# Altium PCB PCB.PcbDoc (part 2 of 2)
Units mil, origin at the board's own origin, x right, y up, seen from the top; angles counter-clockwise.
Board outline 5216.54 x 1820.87 mil, 2 copper layers (Top Layer, Bottom Layer), stack 62 mil thick; 55 components, 32 nets, 136 pads, 25 vias.
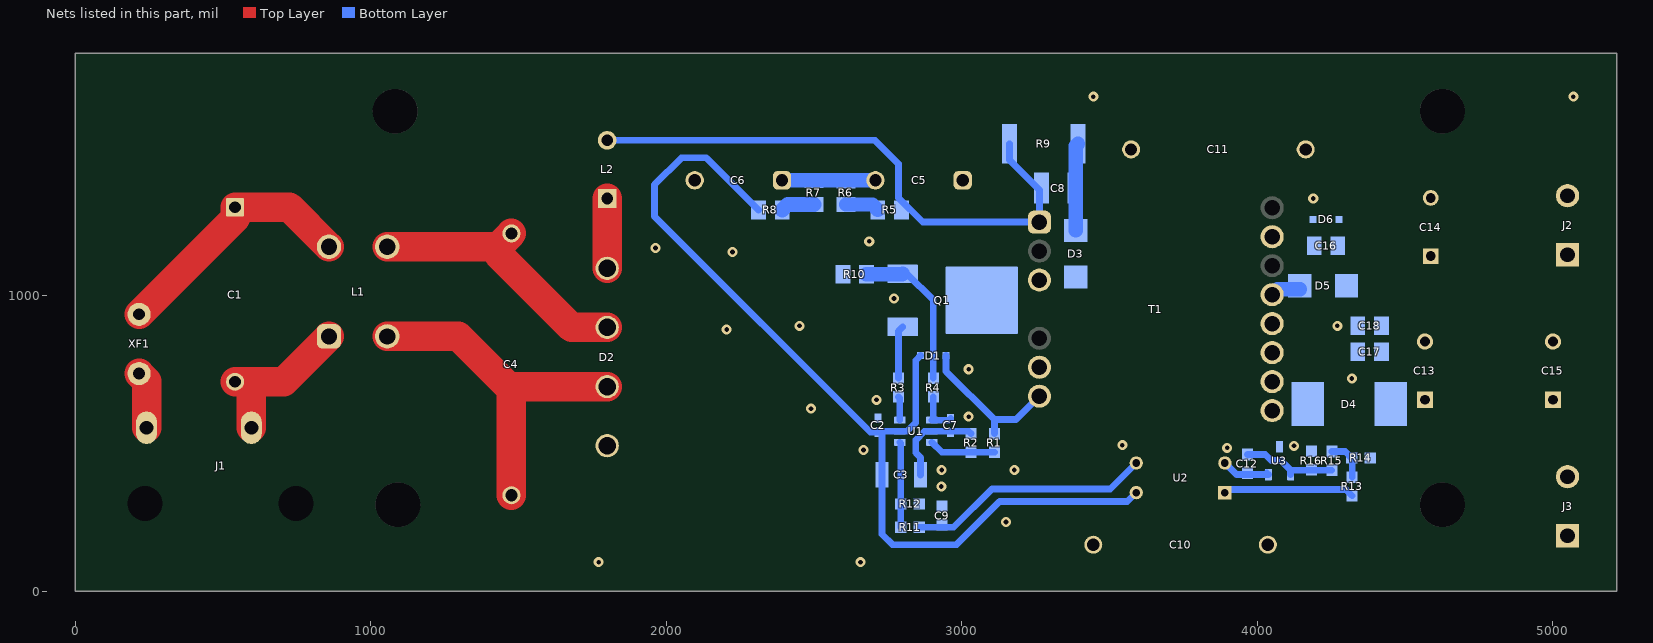
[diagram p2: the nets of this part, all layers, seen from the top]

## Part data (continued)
R13: library part CMP-0022588-5, "RES, 750, 1%, 0.1 W, AEC-Q200 Grade 0, 0603", Manufacturer=Vishay-Dale, Power_W=100mW, Supplier Part Number 1=541-750HCT-ND, TempCo="100 ppm/C", Tolerance_%=1%, Value2=0.1W, Value_Code=750R, ValueDisplayed=750
R14: library part CMP-0025697-4, "RES, 0, 5%, 0.1 W, AEC-Q200 Grade 0, 0603", Manufacturer=Vishay-Dale, Power_W=100mW, Supplier Part Number 1=541-0.0GCT-ND, TempCo="200 ppm/C", Tolerance_%=5%, Value2=0.1W, Value_Code=0000, ValueDisplayed=0
R15: library part CMP-0022651-4, "RES, 90.9 k, 1%, 0.1 W, AEC-Q200 Grade 0, 0603", Manufacturer=Vishay-Dale, Power_W=100mW, Supplier Part Number 1=541-90.9KHCT-ND, TempCo="100 ppm/C", Tolerance_%=1%, Value2=0.1W, Value_Code=90k9, ValueDisplayed=90.9k
R16: library part CMP-0022410-4, "RES, 40.2 k, 1%, 0.1 W, AEC-Q200 Grade 0, 0603", Manufacturer=Vishay-Dale, Power_W=100mW, Supplier Part Number 1=541-40.2KHCT-ND, TempCo="100 ppm/C", Tolerance_%=1%, Value2=0.1W, Value_Code=40k2, ValueDisplayed=40.2k
T1: library part CMP-0081896-1, "Transformer, 2900 uH, TH", Manufacturer="Wurth Elektronik"
U1: library part CMP-0078369-1, "High-Efficiency Low-Cost Flyback Controller with Secondary-Side Regulation, DBV0006A (SOT-23-6)", Alternate Manufacturer="Texas Instruments"
U2: library part CMP-0006173-1, "Optocoupler, 5 kV, 80-160% CTR, TH", Manufacturer="Fairchild Semiconductor", Supplier Part Number 1=FOD817A-ND, Voltage_Isolation_Vrms=5kV
U3: library part CMP-0033048-1, "Low Voltage Adjustable Precision Shunt Regulator, 39 ppm / degC, 15 mA, 0 to 70 degC, 3-pin SOT-23 (DBZ), Green (RoHS & no Sb/Br)", Manufacturer="Texas Instruments", Rating=Catalog, Temp Coeff(Max)(ppm/ degree C)=129, Temp Coeff(Typ)(ppm/ degree C)=39
XF1: library part CMP-0003627-1, "Fuse Holder, TR5, TH", Manufacturer=Littelfuse, Supplier Part Number 1=WK6235-ND

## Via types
v1: diameter 34, hole 16, Top Layer to Bottom Layer, 24 vias
v2: diameter 34, hole 16, Top Layer to Bottom Layer, tented both sides, 1 vias

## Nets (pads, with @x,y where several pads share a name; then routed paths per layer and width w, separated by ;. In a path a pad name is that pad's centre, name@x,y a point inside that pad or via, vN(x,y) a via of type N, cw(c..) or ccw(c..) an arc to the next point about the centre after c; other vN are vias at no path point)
AGND: C11.1 C14.2 C16.2 D6.2 J2.2 T1.13
  other v1: 4188.97,1328.74 5068.9,1673.23
Bias: D1.2 R1.2 T1.6 | length 516.8
  Bottom Layer w23: D1.2@2946.85,797.24 2946.85,744.09 3110.24,580.71 ; R1.2@3110.24,533.25 3110.24,580.71 ; T1.6@3262.62,659.82 3183.51,580.71 3110.24,580.71
FB: R11.1 R12.2 U1.1 | length 288.6
  Bottom Layer w23: U1.1@2790.35,503.94 2793.31,500.98 R11.1@2793.31,216.54
NetC1_1: C1.1 L1.4 XF1.1 | length 870.3
  Top Layer w100: XF1.1@216.54,936.61 541.34,1261.42 C1.1@541.34,1299.21 725.24,1299.21 L1.4@859.09,1165.35
NetC1_2: C1.2 J1.2 L1.1 | length 538.5
  Top Layer w100: C1.2@541.34,708.66 600.39,708.66 ; J1.2@596.46,553.15 596.46,704.72 600.39,708.66 ; L1.1@859.09,862.2 705.55,708.66 600.39,708.66
NetC4_1: C4.1 D2.3 L1.2 | length 1172.4
  Top Layer w100: L1.2@1055.94,862.2 1296.85,862.2 1466.54,692.52 ; C4.1@1476.38,324.8 1476.38,692.52 D2.3@1800.17,692.52
NetC4_2: C4.2 D2.2 L1.3 | length 935.1
  Top Layer w100: L1.3@1055.94,1165.35 1431.1,1165.35 ; C4.2@1476.38,1210.63 1431.1,1165.35 ; D2.2@1800.17,892.52 1680.31,892.52 1431.1,1141.72 1431.1,1165.35
NetC5_2: C5.2 C6.1 R6.1 R7.2 | length 315.9
  Bottom Layer w50: C6.1@2391.73,1390.38 C5.2@2707.68,1390.38
NetC7_1: C7.1 R4.1 U1.4 | length 147.2
  Bottom Layer w23: R4.1@2903.54,657.46 2903.54,583.66 U1.4@2898.62,578.74 2956.69,578.74 C7.1@2962.6,584.65
NetC8_2: C8.2 D3.1 R9.1 | length 296.6
  Bottom Layer w48: D3.1@3385.83,1220.47 3385.83,1506.44 R9.1@3393.33,1513.95
NetC9_1: C9.1 R11.2 U2.3 | length 823.9
  Bottom Layer w23: R11.2@2856.3,216.54 2972.44,216.54 3101.92,346.01 3502.31,346.01 U2.3@3590.16,433.86
NetC12_1: C12.1 R15.1 R16.2 U3.1 | length 322.3
  Bottom Layer w23: C12.1@3966.53,462.77 4026.65,462.77 4047.45,441.97 4079.85,441.97 U3.1@4112.2,409.62 ; U3.1@4112.2,394.72 U3.1@4112.2,409.62 ; R15.1@4251.96,409.62 U3.1@4112.2,409.62
NetC12_2: C12.2 U2.2 U3.2 | length 171.7
  Bottom Layer w23: U2.2@3890.16,433.86 3929.29,394.72 U3.2@4037.4,394.72 U3.2@4031.56,400.56
NetD2_1: D2.1 L2.1 | length 236.2
  Top Layer w100: D2.1@1800.17,1092.52 L2.1@1800.17,1328.74
NetD3_2: D3.2 Q1.4 T1.3
NetD4_2: D4.2 T1.7 T1.8
NetD5_2: D5.2 T1.11 | length 101.3
  Bottom Layer w48: T1.11@4050.02,1003.33 4068.46,1021.76 D5.2@4143.7,1021.76
NetJ1_1: J1.1 XF1.2 | length 194.1
  Top Layer w100: XF1.2@216.54,736.61 242.13,711.02 J1.1@242.13,553.15
NetQ1_1: Q1.1 R3.2 | length 180.1
  Bottom Layer w23: R3.2@2785.43,720.45 2785.43,879.9 Q1.1@2800.02,894.49
NetQ1_3: Q1.3 R4.2 R10.2 | length 527.7
  Bottom Layer w23: Q1.3@2800.02,1074.02 2814.59,1074.02 2903.54,985.06 R4.2@2903.54,720.45
  Bottom Layer w50: R10.2@2677.8,1072.83 2798.84,1072.83 Q1.3@2800.02,1074.02
NetR1_1: R1.1 R2.2 U1.6 | length 225.6
  Bottom Layer w23: U1.6@2898.62,503.94 2932.3,470.26 R1.1@3110.24,470.26
NetR3_1: R3.1 U1.3 | length 80.8
  Bottom Layer w23: R3.1@2785.43,657.46 2790.35,652.54 U1.3@2790.35,578.74
NetR5_1: R5.1 R6.2 | length 115.3
  Bottom Layer w48: R6.2@2608.27,1308.43 2697.47,1308.43 R5.1@2715.91,1289.98
NetR7_1: R7.1 R8.2 | length 115.4
  Bottom Layer w50: R8.2@2392.36,1289.98 2411.12,1308.74 R7.1@2500,1308.74
NetR13_1: R13.1 U2.1 | length 444
  Bottom Layer w23: U2.1@3890.16,333.86 3900.79,344.49 4299.51,344.49 R13.1@4320.86,323.14
NetR13_2: R13.2 R14.1 R15.2 | length 141.5
  Bottom Layer w23: R15.2@4251.96,472.61 4297.24,472.61 R14.1@4318.89,450.95 4320.86,448.99 R13.2@4320.86,386.13
PGND: C2.2 C3.2 C6.2 C7.2 C9.2 C10.2 C11.2 D2.4 R2.1 R10.1 R12.1 T1.5 U1.5 | length 327.2
  Bottom Layer w23: C3.2@2860.24,393.7 2860.24,452.76 2844.49,468.5 2844.49,511.81 2874.02,541.34 U1.5@2898.62,541.34 3023.41,541.34 R2.1@3031.5,533.25
  other v1: 1771.65,98.43 2657.48,98.43 3149.61,234.62 2930.81,354.33 2932.09,410.47 3177.59,410.47 2667.77,478.27 3543.31,494.13 3023.41,590.55 2490.16,617.78 2711.8,647.8 3023.41,751.14 2204.72,885.83 2450.79,898.17 2770.44,990.16 2224.41,1147.83 1963.56,1161.42 2687.01,1183.69 3445.2,1673.23
SGND: C10.1 C13.2 C15.2 C17.2 C18.2 J3.1 R16.1 T1.9 T1.10 U3.3
  other v1: 3897.64,485.23 4319.71,720.06 4270.67,898.17
  other v2: 4124.02,492.13
Vaux: C14.1 C16.1 D5.1 D6.1 J2.1
VBulk: C5.1 C8.1 L2.2 R5.2 R9.2 T1.1 | length 1952
  Bottom Layer w23: L2.2@1800.17,1525.59 2706.69,1525.59 2786.06,1446.22 2786.06,1330.69 2867.96,1248.8 T1.1@3262.62,1248.8 3262.62,1357.1 3161.05,1458.67 R9.2@3161.05,1513.95
VDD: C2.1 C3.1 D1.1 R8.1 U1.2 U2.4 | length 3309.4
  Bottom Layer w23: R8.1@2312.36,1289.98 2135.81,1466.54 2051.67,1466.54 1960.67,1375.54 1960.67,1267.67 2690.23,538.11 C2.1@2716.54,538.11 ; D1.1@2860.24,797.24 2844.49,781.5 2844.49,570.87 2814.96,541.34 U1.2@2790.35,541.34 2719.76,541.34 C2.1@2716.54,538.11 ; U2.4@3590.16,333.86 3559.75,303.45 3128.25,303.45 2982.28,157.48 2765.75,157.48 2730.32,192.91 C3.1@2730.32,393.7 2730.32,538.11 C2.1@2716.54,538.11
Vout: C13.1 C15.1 C17.1 C18.1 D4.1 J3.2 R14.2
pads on no net: H1.0 H1.MH H2.0 H2.MH H3.0 H3.MH H4.0 H4.MH J1.MH1 J1.MH2 T1.2 T1.4 T1.12 T1.14

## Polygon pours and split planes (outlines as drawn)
PGND on Bottom Layer "BOTTOM_LAYER_PGND_P016" (solid, remove dead copper, pour order 16): 3612.2,49.21 3612.2,1771.65 1919.29,1771.65 1919.29,639.76 1870.08,590.55 1712.6,590.55 1712.6,49.21
VBulk on Bottom Layer "BOTTOM_LAYER_VBULK_P014" (solid, remove dead copper, pour order 14): 3326.77,1771.65
VBulk on Bottom Layer "BOTTOM_LAYER_VBULK_P000" (solid, remove dead copper, pour order 0): 1722.44,1771.65 1722.44,1476.38 1801.18,1397.64 2717.5,1397.64 2755.91,1359.24 2755.91,1141.73 3326.77,1141.73 3326.77,1771.65
SGND on Bottom Layer "BOTTOM_LAYER_SGND_P012" (solid, remove dead copper, pour order 12): 5167.32,944.88 3868.11,944.88 3868.11,49.21 5167.32,49.21
NetD4_2 on Bottom Layer "BOTTOM_LAYER_NETD4_2_P010" (solid, remove dead copper, pour order 10): 4005.91,748.03 4192.91,748.03 4232.28,708.66 4232.28,551.18 4045.28,551.18 4005.91,590.55
Vout on Bottom Layer "BOTTOM_LAYER_VOUT_P008" (solid, remove dead copper, pour order 8): 5167.32,944.88 4379.92,944.88 4379.92,295.28 5167.32,295.28
AGND on Bottom Layer "BOTTOM_LAYER_AGND_P006" (solid, remove dead copper, pour order 6): 3937.01,1122.05 3937.01,1771.65 5167.32,1771.65 5167.32,1122.05
Vaux on Bottom Layer "BOTTOM_LAYER_VAUX_P004" (solid, remove dead copper, pour order 4): 4232.28,1279.53 5167.32,1279.53 5167.32,984.25 4232.28,984.25
NetD3_2 on Bottom Layer "BOTTOM_LAYER_NETD3_2_P002" (solid, remove dead copper, pour order 2): 2933.07,1112.2 3444.88,1112.2 3444.88,1033.46 3277.56,866.14 2933.07,866.14
SGND on Top Layer "TOP_LAYER_SGND_P022" (solid, remove dead copper, pour order 22): 5167.32,944.88 3868.11,944.88 3868.11,49.21 5167.32,49.21
AGND on Top Layer "TOP_LAYER_AGND_P020" (solid, remove dead copper, pour order 20): 5167.32,1771.65 3937.01,1771.65 3937.01,984.25 5167.32,984.25
PGND on Top Layer "TOP_LAYER_PGND_P018" (solid, remove dead copper, pour order 18): 3612.2,1771.65 1919.29,1771.65 1919.29,639.76 1870.08,590.55 1712.6,590.55 1712.6,49.21 3612.2,49.21

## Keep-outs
Keep-Out Layer:
  text ".Layer_Name" at 577,-858.49 h60

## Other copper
Top Layer:
  text ".Layer_Name" at 577,-858.49 h60
Bottom Layer:
  text ".Layer_Name" at 577,-858.49 h60

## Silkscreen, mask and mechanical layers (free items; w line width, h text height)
Top Overlay:
  text "'.PRJ_Number'.PCB_Rev" at 157.48,1555.12 h108.27
  text ".Layer_Name" at 577,-858.49 h60
Bottom Overlay:
  lines w10: 2499.36,472.42 2578.73,472.42 2578.73,541.12 2499.36,541.12 2499.36,472.42
  text ".Layer_Name" at 577,-858.49 h60
Top Paste:
  text ".Layer_Name" at 577,-858.49 h60
Bottom Paste:
  text ".Layer_Name" at 577,-858.49 h60
Top Solder:
  text ".Layer_Name" at 577,-858.49 h60
  text ".Layer_Name" at 577,-858.49 h60
Bottom Solder:
  text ".Layer_Name" at 577,-858.49 h60
Drill Guide:
  text ".Layer_Name" at 577,-858.49 h60
M1 Board Outline:
  the board outline again, w10
  text ".Layer_Name" at 577,-858.49 h60
M2 Board Dimensions:
  rectangle: 0,-275 125,-150
  rectangle: 125,-400 500,-275
  lines w7: 0,-275 1000,-275 ; 125,-400 125,-150 ; 250,-400 250,-150 ; 500,-400 500,-150 ; 750,-400 750,-150 ; 0,-400 1000,-400 1000,-150 0,-150 0,-400
  text ".Layer_Name" at 577,-858.49 h60
M3 3D STEP Top:
  text ".Layer_Name" at 577,-858.49 h60
M4 3D STEP Bottom:
  text ".Layer_Name" at 577,-858.49 h60
M5 Assembly Top:
  lines w10: -292,-930.17 6308,-930.17 ; -292,-726.83 6310,-726.83 ; -292,-523.5 -292,-1133.5 3713,-1133.5 6310,-1133.5 6310,-523.5 -291.5,-523.5 -291.5,-1133.5 1284,-1133.5 ; 2173,-1133.5 2173,-523.5 ; 3440,-726.83 3440,-523.5 ; 4280,-726.83 4280,-523.5 ; 4902,-1140 4902,-937.17
  text "COMPONENTS MARKED 'DNP' SHOULD NOT BE POPULATED." at 1153.5,-318.5 h60
  text "ASSEMBLY VARIANT:" at 1153,-434 h60
  text ".VariantName" at 2189,-434 h60
  text "PCB VIEWED FROM TOP SIDE" at -228.5,-655.67 h60
  text "BOARD #:" at 2248,-655.67 h60
  text ".PRJ_Number" at 2793.5,-655.67 h60
  text "REV:" at 3638,-655.67 h60
  text ".PCB_Rev" at 3929.5,-655.67 h60
  text "SVN REV:" at 4476,-655.67 h60
  text ".VersionControl_RevNumber" at 4982,-655.67 h60
  text "TID #:" at 2248,-859 h60
  text ".TID" at 2793.5,-859 h60
  text "PLOT NAME =" at -228.5,-1064.34 h60
  text ".plot_File_Name" at 577,-1064.34 h60
  text "GENERATED    :" at 2250,-1064.34 h60
  text ".Print_Date" at 3119.5,-1064.34 h60
  text ".Print_Time" at 3848.5,-1064.34 h60
  text "TEXAS INSTRUMENTS" at 5113,-1064.34 h60
M6 Assembly Bottom:
  lines w10: -292.5,-727.33 6309.5,-727.33 ; -290.5,-930.67 6309.5,-930.67 ; 1115.5,-1140.5 1115.5,-937.67 ; 1737.5,-727.33 1737.5,-524 ; 2577.5,-727.33 2577.5,-524 ; 3844.5,-1134 3844.5,-524 ; 4733.5,-1134 6309,-1134 6309,-524 -292.5,-524 -292.5,-1134 2304.5,-1134 6309.5,-1134 6309.5,-524
  text "COMPONENTS MARKED 'DNP' SHOULD NOT BE POPULATED." at 6102,-318 h60
  text ".VariantName" at 5058,-434 h60
  text "ASSEMBLY VARIANT:" at 6097,-434 h60
  text ".VersionControl_RevNumber" at 1035.5,-656.17 h60
  text "SVN REV:" at 1541.5,-656.17 h60
  text ".PCB_Rev" at 2088,-656.17 h60
  text "REV:" at 2379.5,-656.17 h60
  text ".PRJ_Number" at 3224,-656.17 h60
  text "BOARD #:" at 3769.5,-656.17 h60
  text "PCB VIEWED FROM BOTTOM SIDE" at 6246,-656.17 h60
  text ".TID" at 3224,-859.5 h60
  text "TID #:" at 3769.5,-859.5 h60
  text "TEXAS INSTRUMENTS" at 904.5,-1064.84 h60
  text ".Print_Time" at 2169,-1064.84 h60
  text ".Print_Date" at 2898,-1064.84 h60
  text "GENERATED    :" at 3767.5,-1064.84 h60
  text ".plot_File_Name" at 5440.5,-1064.84 h60
  text "PLOT NAME =" at 6246,-1064.84 h60
M9 Title Sheet:
  drawing of 57 lines, arcs and shapes, not listed
  text "1" at 739.84,8036.5 h70
  text "2" at 3235.5,8036.5 h70
  text "3" at 5724.84,8036.5 h70
  text "4" at 8231.51,8036.5 h70
  text "5" at 10730.5,8036.5 h70
  text "6" at 13235.5,8036.5 h70
  text "A" at -416.5,6893.5 h70
  text "A" at 14383.5,6893.5 h70
  text "B" at -416.5,4513.5 h70
  text "B" at 14383.5,4513.5 h70
  text "C" at -416.5,2138.5 h70
  text "C" at 14383.5,2138.5 h70
  text "PROJECT TITLE:" at 11343.5,277.5 h45
  text ".PRJ_Title" at 11393.5,144.17 h70
  text "DESIGNED FOR:" at 11343.5,-23.5 h45
  text ".PRJ_Customer" at 11393.5,-163.5 h70
  text "D" at -416.5,-231.5 h70
  text "D" at 14383.5,-231.5 h70
  text "FILE NAME:" at 11343.5,-323.5 h45
  text ".PCB_File_Name_No_Path" at 11393.5,-443.5 h70
  text "Texas Instruments (TI) and/or its licensors do not warrant the accuracy or completeness of this specification" at 6374,-605.34 h45
  text "ENGINEER:" at 11343.5,-613.5 h45
  text "LAYOUT BY:" at 12848.5,-613.5 h45
  text "or any information contained therein. TI and/or its licensors do not warrant that this design will meet" at 6329.01,-718 h45
  text ".PRJ_Engineer" at 11393.5,-768.49 h70
  text ".PCB_Layout" at 12899,-768.49 h70
  text "the specifications, will be suitable for your application or fit for any particular purpose, or will operate in" at 6329.01,-830.67 h45
  text ".Layer_Name" at 577,-858.49 h60
  text "ALTIUM DESIGNER VERSION:" at 12848.5,-923.5 h45
  text "an implementation. TI and/or its licensors do not warrant that the design is production worthy. You should" at 6329.01,-943.33 h45
  text "completely validate and test your design implementation to confirm the system functionality for your application." at 6374,-1056 h45
  text ".print_Scale" at 11393.5,-1056.83 h70
  text ".Application_BuildNumber" at 12899,-1056.83 h70
  text "1" at 739.84,-1263.5 h70
  text "2" at 3235.5,-1263.5 h70
  text "3" at 5724.84,-1263.5 h70
  text "4" at 8231.51,-1263.5 h70
  text "5" at 10730.5,-1263.5 h70
  text "6" at 13235.5,-1263.5 h70
M10 Fab Notes:
  drawing of 189 lines, arcs and shapes, not listed
  text "DESIGN INFORMATION" at 12382.02,6356.17 h60
  text "MIN. TRACK WIDTH:" at 11737.46,6224.05 h60
  text "8" at 12833.7,6224.05 h60
  text "MIL" at 12988.46,6224.05 h60
  text "MIN. CLEARANCE:" at 11737.46,6099.92 h60
  text "0.2" at 12773.7,6099.93 h60
  text "mm" at 12988.46,6099.92 h60
  text "MIN. VIA PAD SIZE:" at 11737.46,5975.8 h60
  text "24" at 12803.71,5975.8 h60
  text "MIL" at 12988.46,5975.8 h60
  text "0.05mm (2MIL)" at 12432.46,5845.9 h60
  text "MINIMUM ANNULAR RING" at 11408.23,5837.67 h60
  text "EXTERNAL" at 13140.46,5837.67 h60
  text "PER" at 11608.23,5727.55 h60
  text "IPC-D-275 CLASS 2 LEVEL C" at 11828.23,5727.54 h60
  text "MIL, HOLES" at 13316.46,5627.07 h60
  text "+/-" at 12924,5618.48 h60
  text "+/-" at 13778,5618.48 h60
  text "REGISTRATION TOLERANCES:" at 11408.23,5617.42 h60
  text "METAL" at 12608,5617.42 h60
  text "5" at 13184.2,5617.42 h60
  text "3" at 14017.2,5617.42 h60
  text "MIL" at 14133.46,5617.42 h60
  text "HOLE SIZE TOLERANCE (UNLESS OTHERWISE SPECIFIED):" at 11408.23,5519.1 h60
  text "+/-" at 13778,5516.23 h60
  text "3" at 14017.2,5515.17 h60
  text "MIL" at 14133.46,5515.17 h60
  text "MATERIAL:" at 11333.46,5377.52 h60
  text "FR-4 High Tg" at 12319.9,5249 h60
  text "X" at 12175.46,5241.01 h60
  text "FR-408" at 11754.46,5236.49 h60
  text "OTHER" at 13242.46,5236.49 h60
  text "62 MIL (1.6mm) +/-10%" at 12074.56,5093.46 h60
  text "X" at 11954.46,5091.01 h60
  text "THICKNESS:" at 11408.23,5085.24 h60
  text "OTHER" at 13359.46,5085.24 h60
  text "TOLERANCE:" at 11408.23,4946.92 h60
  text "X" at 12256.46,4946.92 h60
  text "ANSI IPC-6012 TYPE 3 CLASS 2" at 12434.48,4946.92 h60
  text "OTHER +/-" at 12434.46,4802.73 h60
  text "BOW & TWIST:" at 11408.23,4657.54 h60
  text "X" at 12256.46,4657.54 h60
  text "ANSI IPC-6012 TYPE 3 CLASS 2" at 12434.48,4657.54 h60
  text "OTHER +/-" at 12434.46,4510.85 h60
  text "DRILLING:" at 11333.46,4380.23 h60
  text "NC_DRILL FILES" at 13094.46,4275.04 h60
  text "REFERENCE:" at 11408.23,4271.1 h60
  text "X" at 12065.46,4271.01 h60
  text "AS SHOWN" at 12243.46,4271.1 h60
  text "X" at 12966.46,4271.1 h60
  text "OTHER" at 13392.46,4128.85 h60
  text "PTH COPPER THICKNESS:" at 11407.91,4125.32 h60
  text "X" at 12547.14,4125.32 h60
  text "20-30 um" at 12675.14,4125.32 h60
  text "BOARD FINISH:" at 11333.46,3977.73 h60
  text "SILKSCREEN:" at 11488.68,3867.6 h60
  text "X" at 12446.46,3867.6 h60
  text "TOP" at 12563.46,3867.6 h60
  text "X" at 12956.46,3867.6 h60
  text "BOTTOM" at 13074.46,3867.6 h60
  text "SILKSCREEN COLOR:" at 11488.68,3712.41 h60
  text "X" at 12445.46,3712.41 h60
  text "WHITE" at 12563.46,3712.41 h60
  text "OTHER" at 13074.46,3712.41 h60
  text "X" at 12576.46,3568.96 h60
  text "GREEN" at 12694.46,3568.96 h60
  text "OTHER" at 13312.46,3568.96 h60
  text "SOLDER RESIST COLOR:" at 11488.68,3562.1 h60
  text "X" at 12576.46,3414.71 h60
  text "MATTE" at 12694.46,3414.71 h60
  text "SEMI-GLOSS" at 13312,3414.07 h60
  text "IMMERSION GOLD (ENIG)" at 12394.46,3241.94 h60
  text "ENEPIG" at 13732,3234.72 h60
  text "SURFACE FINISH:" at 11333.46,3233.72 h60
  text "X" at 12216.46,3233.72 h60
  text "IMM. TIN/SILVER OR EQUIV" at 11663,3096.4 h60
  text "OTHER" at 13094.46,3092.47 h60
  text "ARRAY/PANEL:" at 11333.46,2937.09 h60
  text "CUT AND TRIM PER M1 BOARD OUTLINE" at 12394.46,2928.87 h60
  text "N.C. ROUTE" at 12394.46,2792.9 h60
  text "X" at 13082.46,2792.9 h60
  text "V. SCORE" at 13260.46,2792.9 h60
  text "CERTIFICATION:" at 11333.46,2663.77 h60
  text "MATERIALS AND WORKMANSHIP FOR ALL PCBS" at 12058.46,2663.77 h60
  text "TO MEET OR EXCEED THE REQUIREMENTS OF:" at 12058.46,2569.71 h60
  text "X" at 11695.97,2441.08 h60
  text "ANSI IPC-A-600F CLASS ->" at 11823.96,2441.08 h60
  text "X" at 13471.97,2441.08 h60
  text "2" at 13581.96,2441.08 h60
  text "1" at 13266.96,2439.58 h60
  text "3" at 13935.96,2439.58 h60
  text "X" at 12507.97,2293.39 h60
  text "RoHS" at 12635.96,2293.39 h60
  text "OTHER" at 13280.36,2293.39 h60
  text "PER ORDER" at 13677.42,2293.39 h60
  text "ALL BOARDS MUST MEET OR EXCEED UL94-V0 REQUIREMENTS." at 11361,2139.57 h60
  text "PCB MUST BEAR THE UL94V-0 UL REGISTERED MATERIAL ID NUMBER" at 11361,2023.5 h60
  text "ADDITIONAL REQUIREMENTS:" at 11333.46,1854.08 h60
  text "MICROSECTION:" at 11408.23,1746.95 h60
  text "YES" at 12313.96,1746.95 h60
  text "REQUIRED" at 13175.46,1602.62 h60
  text "BARE BOARD ELEC. TEST:" at 11408.23,1599.76 h60
  text "NONE" at 12713.96,1599.76 h60
  text "X" at 13057.46,1599.76 h60
  text "PER ORDER" at 13767.46,1599.76 h60
  text "XX MIL VIAS REQUIRE NON-CONDUCTIVE FILL AND PLANARIZE" at 11576.38,1394.82 h59
  text "XX MIL VIAS REQUIRE CONDUCTIVE FILL AND PLANARIZE" at 11584.38,1290.84 h60
  text "OUTER XX MIL TRACES REQUIRE 50 OHM SINGLE-ENDED IMPEDANCE" at 11583.39,1127.46 h58
  text "LAYER 2 & 3 (INNER LAYERS) XX MIL WIDE, XX MIL SPACE / TRACES REQUIRE 100 OHM DIFFERENTIAL IMPEDANCE" at 11575.39,891.74 h60
  text ".Layer_Name" at 577,-858.49 h60
M11 Gerber Information:
  lines w10: -292,-930.17 6308,-930.17 ; -292,-726.83 6310,-726.83 ; -292,-523.5 -292,-1133.5 3713,-1133.5 6310,-1133.5 6310,-523.5 -291.5,-523.5 -291.5,-1133.5 1284,-1133.5 ; 2173,-1133.5 2173,-523.5 ; 3440,-726.83 3440,-523.5 ; 4280,-726.83 4280,-523.5 ; 4902,-1140 4902,-937.17
  text "ALL ARTWORK VIEWED FROM TOP SIDE" at -228.5,-655.67 h60
  text "BOARD #:" at 2248,-655.67 h60
  text ".PRJ_Number" at 2793.5,-655.67 h60
  text "REV:" at 3638,-655.67 h60
  text ".PCB_Rev" at 3929.5,-655.67 h60
  text "SVN REV:" at 4476,-655.67 h60
  text ".VersionControl_RevNumber" at 4982,-655.67 h60
  text "LAYER NAME =" at -228.5,-858.49 h60
  text "TID #:" at 2248,-859 h60
  text ".TID" at 2793.5,-859 h60
  text "PLOT NAME =" at -228.5,-1064.34 h60
  text ".plot_File_Name" at 577,-1064.34 h60
  text "GENERATED    :" at 2250,-1064.34 h60
  text ".Print_Date" at 3119.5,-1064.34 h60
  text ".Print_Time" at 3848.5,-1064.34 h60
  text "TEXAS INSTRUMENTS" at 5113,-1064.34 h60
M12 Stackup:
  drawing of 191 lines, arcs and shapes, not listed
  text "Layer" at 9797.84,7492.5 h60
  text "Name" at 10207.76,7492.5 h60
  text "Material" at 11137.5,7492.5 h60
  text "Thickness" at 11997.27,7492.5 h60
  text "Constant" at 12647.1,7492.5 h60
  text "Board Layer Stack" at 13216.96,7492.5 h60
  text "1" at 9797.84,7372.5 h60
  text "Top Overlay" at 10207.76,7372.5 h60
  text "2" at 9797.84,7252.5 h60
  text "Top Solder" at 10207.76,7252.5 h60
  text "Solder Resist" at 11137.5,7252.5 h60
  text "0.40mil" at 11997.27,7252.5 h60
  text "3.5" at 12647.1,7252.5 h60
  text "3" at 9797.84,7132.5 h60
  text "Top Layer" at 10207.76,7132.5 h60
  text "Copper" at 11137.5,7132.5 h60
  text "1.40mil" at 11997.27,7132.5 h60
  text "4" at 9797.84,7012.5 h60
  text "Dielectric1" at 10207.76,7012.5 h60
  text "FR-4" at 11137.5,7012.5 h60
  text "59.20mil" at 11997.27,7012.5 h60
  text "4.8" at 12647.1,7012.5 h60
  text "5" at 9797.84,6892.5 h60
  text "Bottom Layer" at 10207.76,6892.5 h60
  text "Copper" at 11137.5,6892.5 h60
  text "1.40mil" at 11997.27,6892.5 h60
  text "6" at 9797.84,6772.5 h60
  text "Bottom Solder" at 10207.76,6772.5 h60
  text "Solder Resist" at 11137.5,6772.5 h60
  text "0.40mil" at 11997.27,6772.5 h60
  text "3.5" at 12647.1,6772.5 h60
  text "7" at 9797.84,6652.5 h60
  text "Bottom Overlay" at 10207.76,6652.5 h60
  text ".Layer_Name" at 577,-858.49 h60
M13 Component Bodies Top:
  text ".Layer_Name" at 577,-858.49 h60
M14 Component Bodies Bottom:
  text ".Layer_Name" at 577,-858.49 h60
M15 Courtyards Top:
  text ".Layer_Name" at 577,-858.49 h60
M16 Courtyards Bottom:
  text ".Layer_Name" at 577,-858.49 h60
Drill Drawing:
  circle w10: c6382.93,2063.5 r16.58
  circle w10: c6382.93,2063.5 r27.63
  circle w10: c6382.93,1193.26 r27.63
  lines w10: 6355.3,1055.13 6369.12,1055.13 6369.12,1041.32 6396.74,1041.32 6396.74,1055.13 6410.56,1055.13 6410.56,1082.76 6396.74,1082.76 6396.74,1096.57 6369.12,1096.57 6369.12,1082.76 6355.3,1082.76 6355.3,1055.13 ; 6355.3,1303.77 6369.12,1303.77 6382.93,1289.96 6396.74,1303.77 6410.56,1303.77 6396.74,1317.58 6410.56,1331.4 6396.74,1331.4 6382.93,1345.21 6369.12,1331.4 6355.3,1331.4 6369.12,1317.58 6355.3,1303.77 ; 6355.3,1414.28 6355.3,1428.09 6369.12,1441.9 6355.3,1455.72 6355.3,1469.53 6369.12,1469.53 6382.93,1455.72 6396.74,1469.53 6410.56,1469.53 6410.56,1455.72 6396.74,1441.9 6410.56,1428.09 6410.56,1414.28 6396.74,1414.28 6382.93,1428.09 6369.12,1414.28 6355.3,1414.28 ; 6355.3,1593.85 6410.56,1593.85 6382.93,1538.6 6355.3,1593.85 ; 6355.3,1787.24 6410.56,1787.24 6410.56,1842.49 6355.3,1842.49 6355.3,1787.24 ; 6355.3,1966.81 6410.56,1966.81 6382.93,1911.56 6355.3,1966.81 ; 6355.3,2174.01 6369.12,2174.01 6382.93,2160.2 6396.74,2174.01 6410.56,2174.01 6396.74,2187.82 6410.56,2201.64 6396.74,2201.64 6382.93,2215.45 6369.12,2201.64 6355.3,2201.64 6369.12,2187.82 6355.3,2174.01 ; 6355.3,2312.14 6382.93,2284.52 6410.56,2312.14 6382.93,2339.77 6355.3,2312.14 ; 6355.3,2408.84 6382.93,2422.65 6410.56,2408.84 6396.74,2436.46 6410.56,2464.09 6382.93,2450.28 6355.3,2464.09 6369.12,2436.46 6355.3,2408.84 ; 6355.3,2533.16 6382.93,2546.97 6410.56,2533.16 6396.74,2560.78 6410.56,2588.41 6382.93,2574.6 6355.3,2588.41 6369.12,2560.78 6355.3,2533.16 ; 6366.35,1582.8 6399.51,1582.8 6382.93,1549.65 6366.35,1582.8 ; 6366.35,2179.54 6374.64,2179.54 6382.93,2171.25 6391.22,2179.54 6399.51,2179.54 6391.22,2187.82 6399.51,2196.11 6391.22,2196.11 6382.93,2204.4 6374.64,2196.11 6366.35,2196.11 6374.64,2187.82 6366.35,2179.54 ; 6366.35,2419.89 6382.93,2428.18 6399.51,2419.89 6391.22,2436.46 6399.51,2453.04 6382.93,2444.75 6366.35,2453.04 6374.64,2436.46 6366.35,2419.89
  lines w12: 6305.21,1004.02 9536.7,1004.02 ; 6305.21,2620.18 9536.7,2620.18 ; 6643.07,879.7 6643.07,2744.5 ; 6975.08,879.7 6975.08,2744.5 ; 7611.64,879.7 7611.64,2744.5 ; 7870.78,879.7 7870.78,2744.5 ; 8245.94,879.7 8245.94,2744.5 ; 8970.27,879.7 8970.27,2744.5 ; 6305.21,879.7 9536.7,879.7 9536.7,2744.5 6305.21,2744.5 6305.21,879.7
  text "Symbol" at 6379.8,2657.48 h72
  text "Quantity" at 6680.37,2657.48 h72
  text "Finished Hole Size" at 7012.37,2657.48 h72
  text "Plated" at 7648.93,2657.48 h72
  text "Hole Type" at 7908.07,2657.48 h72
  text "Drill Layer Pair" at 8283.23,2657.48 h72
  text "Hole Tolerance" at 9007.56,2657.48 h72
  text "2" at 6680.37,2533.16 h60
  text "118.11mil (3.000mm)" at 7012.37,2533.16 h60
  text "NPTH" at 7648.93,2533.16 h60
  text "Round" at 7908.07,2533.16 h60
  text "Top Layer - Bottom Layer" at 8283.23,2533.16 h60
  text "4" at 6680.37,2408.84 h60
  text "152.00mil (3.861mm)" at 7012.37,2408.84 h60
  text "NPTH" at 7648.93,2408.84 h60
  text "Round" at 7908.07,2408.84 h60
  text "Top Layer - Bottom Layer" at 8283.23,2408.84 h60
  text "25" at 6680.37,2284.52 h60
  text "16.00mil (0.406mm)" at 7012.37,2284.52 h60
  text "PTH" at 7648.93,2284.52 h60
  text "Round" at 7908.07,2284.52 h60
  text "Top Layer - Bottom Layer" at 8283.23,2284.52 h60
  text "4" at 6680.37,2160.2 h60
  text "25.59mil (0.650mm)" at 7012.37,2160.2 h60
  text "PTH" at 7648.93,2160.2 h60
  text "Round" at 7908.07,2160.2 h60
  text "Top Layer - Bottom Layer" at 8283.23,2160.2 h60
  text "4" at 6680.37,2035.88 h60
  text "33.00mil (0.838mm)" at 7012.37,2035.88 h60
  text "PTH" at 7648.93,2035.88 h60
  text "Round" at 7908.07,2035.88 h60
  text "Top Layer - Bottom Layer" at 8283.23,2035.88 h60
  text "2" at 6680.37,1911.56 h60
  text "33.47mil (0.850mm)" at 7012.37,1911.56 h60
  text "PTH" at 7648.93,1911.56 h60
  text "Round" at 7908.07,1911.56 h60
  text "Top Layer - Bottom Layer" at 8283.23,1911.56 h60
  text "6" at 6680.37,1787.24 h60
  text "39.37mil (1.000mm)" at 7012.37,1787.24 h60
  text "PTH" at 7648.93,1787.24 h60
  text "Round" at 7908.07,1787.24 h60
  text "Top Layer - Bottom Layer" at 8283.23,1787.24 h60
  text "10" at 6680.37,1662.92 h60
  text "41.34mil (1.050mm)" at 7012.37,1662.92 h60
  text "PTH" at 7648.93,1662.92 h60
  text "Round" at 7908.07,1662.92 h60
  text "Top Layer - Bottom Layer" at 8283.23,1662.92 h60
  text "A" at 6354.52,1652.93 h55.25
  text "4" at 6680.37,1538.6 h60
  text "49.21mil (1.250mm)" at 7012.37,1538.6 h60
  text "PTH" at 7648.93,1538.6 h60
  text "Round" at 7908.07,1538.6 h60
  text "Top Layer - Bottom Layer" at 8283.23,1538.6 h60
  text "14" at 6680.37,1414.28 h60
  text "51.97mil (1.320mm)" at 7012.37,1414.28 h60
  text "PTH" at 7648.93,1414.28 h60
  text "Round" at 7908.07,1414.28 h60
  text "Top Layer - Bottom Layer" at 8283.23,1414.28 h60
  text "+/-1.18mil" at 9007.56,1414.28 h60
  text "4" at 6680.37,1289.96 h60
  text "55.12mil (1.400mm)" at 7012.37,1289.96 h60
  text "PTH" at 7648.93,1289.96 h60
  text "Round" at 7908.07,1289.96 h60
  text "Top Layer - Bottom Layer" at 8283.23,1289.96 h60
  text "4" at 6680.37,1165.64 h60
  text "59.06mil (1.500mm)" at 7012.37,1165.64 h60
  text "PTH" at 7648.93,1165.64 h60
  text "Round" at 7908.07,1165.64 h60
  text "Top Layer - Bottom Layer" at 8283.23,1165.64 h60
  text "2" at 6680.37,1041.32 h60
  text "47.24mil (1.200mm)" at 7012.37,1041.32 h60
  text "PTH" at 7648.93,1041.32 h60
  text "Slot" at 7908.07,1041.32 h60
  text "Top Layer - Bottom Layer" at 8283.23,1041.32 h60
  text "85 Total" at 6680.37,917 h60
  text "Slot definitions :" at 6379.8,829.97 h60
  text "Routed Path Length" at 6830.52,829.97 h60
  text "= Calculated from tool start centre position to tool end centre position." at 7370.26,829.97 h60
  text "Hole Length" at 6830.52,780.25 h60
  text "= Routed Path Length + Tool Size = Slot length as defined in the PCB layout" at 7170.46,780.25 h60
  text ".Layer_Name" at 577,-858.49 h60
M17 Embedded Cavity:
  text ".Layer_Name" at 577,-858.49 h60
M18 Embedded Assembly:
  text ".Layer_Name" at 577,-858.49 h60
M19 Embedded Keepout:
  text ".Layer_Name" at 577,-858.49 h60

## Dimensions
0,-400 to 1000,-400 on M2 Board Dimensions
0,0 to 0,1820.87 on M2 Board Dimensions
0,0 to 5216.54,0 on M2 Board Dimensions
